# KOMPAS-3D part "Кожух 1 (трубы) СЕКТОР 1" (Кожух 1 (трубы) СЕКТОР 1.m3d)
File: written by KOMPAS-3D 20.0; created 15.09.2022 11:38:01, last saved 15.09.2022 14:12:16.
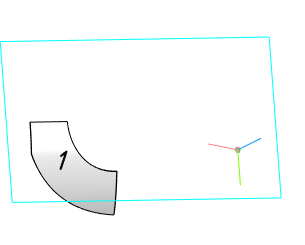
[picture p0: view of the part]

Document properties: Полное имя файла: D:\YAKOVLEV\ПРОЕКТЫ\ДЦ-2. ДП-7 Газопровод Окожушивание\ПРОБА Соединение труб. Окожушивание\Кожух 1 (трубы) СЕКТОР 1.m3d

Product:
- Part/product: Кожух 1 (трубы) СЕКТОР 1
    Материал: Сталь 45  ГОСТ 1050-2013 (density 7810 kg/m3)
    Масса: 92.321

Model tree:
1. Эскиз:1  (with: Обечайка:1)  (labels: Кожух 1 (трубы))
2. Обечайка:1  (labels: Кожух 1 (трубы))
     Расстояние 1 = -2450; Смещение 1 = -50; Толщина листового тела = 20
3. Сгиб(1) - Обечайка:1
     Радиус сгиба = 980; Коэффициент = 0.4; Величина сгиба = 10; Зазор = 1
4. Касательная плоскость:1  (with: Обечайка:1)
5. Эскиз:2  (with: Обечайка:1)  (labels: Кожух 1 (трубы))
6. Вырез в листовом теле:2
     Глубина выреза = 2400
7. Разогнуть:1  (with: Обечайка:1)
8. Эскиз:3  (with: Обечайка:1, Вырез в листовом теле:2)
9. Вырез в листовом теле:3
     Глубина выреза = 1000
10. Эскиз:4  (with: Обечайка:1, Вырез в листовом теле:2, Вырез в листовом теле:3)
11. Вырез в листовом теле:4
     Глубина выреза = 1000
12. Эскиз:5  (with: Обечайка:1, Вырез в листовом теле:3, Вырез в листовом теле:4)
13. Вырез в листовом теле:5
     Глубина выреза = 10
14. Фаска:1  (with: Вырез в листовом теле:2, Вырез в листовом теле:3, Вырез в листовом теле:4)
     Угол = 45; Длина 1 = 3; Длина 2 = 3
15. Эскиз:6  (with: Вырез в листовом теле:5)
16. Вырез в листовом теле:6
     Глубина выреза = 1000
17. Эскиз:7  (with: Обечайка:1)
18. Вырез в листовом теле:7
     Глубина выреза = 0.1
19. Фаска:2  (with: Вырез в листовом теле:6)
     Угол = 20; Длина 1 = 18; Длина 2 = 6.55146
20. Согнуть:1  (with: Обечайка:1)
21. Развертка  (labels: Сталь 45  ГОСТ 1050-2013)

Expressions: v140*2
Referenced files in D:\YAKOVLEV\ПРОЕКТЫ\ДЦ-2. ДП-7 Газопровод Окожушивание\ПРОБА Соединение труб. Окожушивание\: Соединение труб. Окожушивание -2.a3d
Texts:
  Соединение труб. Окожушивание\Труба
